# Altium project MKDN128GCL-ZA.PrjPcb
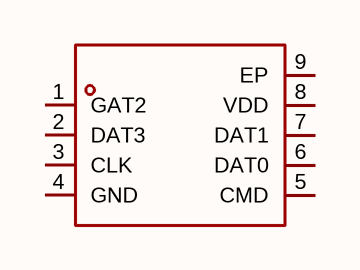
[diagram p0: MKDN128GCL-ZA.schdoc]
1 sheet, 1 parts. Net scope: global (net labels, ports and power ports of the same name join across sheets).

## Sheet MKDN128GCL-ZA.schdoc
size 127 x 101 mm

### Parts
U?  mkdn128gcl-za  [LGA-16_L12.5-W9.0-P1.27-TL-EP]  (value not drawn)

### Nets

Not connected (* = marked no-connect by the designer): U? 1(GAT2) 2(DAT3) 3(CLK) 4(GND) 5(CMD) 6(DAT0) 7(DAT1) 8(VDD) 9(EP)

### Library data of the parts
U? = mkdn128gcl-za: 存储容量:128Gbit;时钟频率(fc):208MHz;工作电压:2.7V~3.6V;; Manufacturer: MK(米客方德); AddInBom: yes; ModelId: aae4acadbbb4480ebd429fe2f08c27d7; ModelTransform: 492.125,354.33,0,0,0,0,0,0,0; Interface: SPI; Clock Frequency: 208MHz; Standby Supply Current: 250uA; ECC: 有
